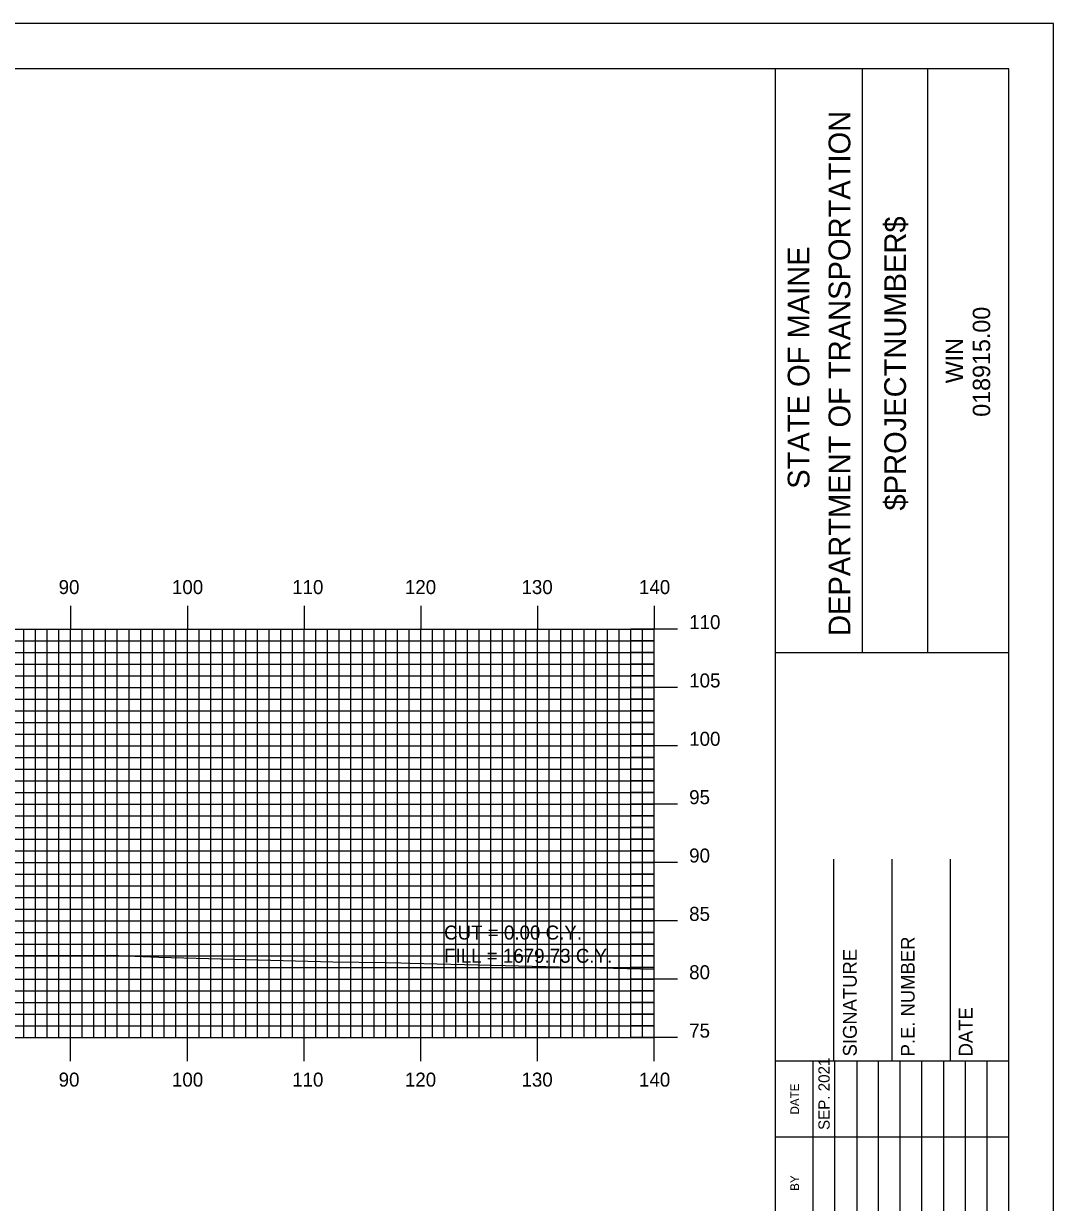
# Model space of a CAD drawing. Extents: x 852542 to 852886, y 364366 to 364586.
# Drawn here: x 852794.1 to 852882.4, y 364484.7 to 364585.7 of the extents above; entities that cross this region are included whole.
import ezdxf

# ---------------------------------------------------------------- set-up
doc = ezdxf.new("R2010")
doc.units = 0
for name, color, linetype in [('BORDER', 7, 'Continuous'), ('D_Text_Standard', 7, 'Continuous'), ('H_V ANNOTATION', 7, 'Continuous'), ('MAJOR', 7, 'Continuous'), ('MINOR', 7, 'Continuous'), ('PLOT BOUNDARY', 7, 'Continuous'), ('S_Roadway_Centerline', 7, 'Continuous')]:
    doc.layers.add(name, color=color, linetype=linetype)

msp = doc.modelspace()

# ---------------------------------------------------------------- linework, layer by layer
at = {"layer": 'BORDER'}
for p, q in [((852858.58, 364371.79), (852858.58, 364581.79)), ((852866.04, 364531.78), (852866.04, 364581.78)), ((852871.63, 364531.78), (852871.63, 364581.78)), ((852858.58, 364531.78), (852878.58, 364531.78)), ((852863.58, 364496.79), (852863.58, 364514.09)), ((852868.58, 364496.79), (852868.58, 364514.09)), ((852873.58, 364496.79), (852873.58, 364514.09)), ((852858.58, 364496.79), (852878.58, 364496.79))]:
    msp.add_line(p, q, dxfattribs=at)
msp.add_lwpolyline([(852558.58, 364371.79), (852878.58, 364371.79), (852878.58, 364581.79), (852558.58, 364581.79)], close=True, dxfattribs=at)
for points in [[(852861.81, 364490.29), (852861.81, 364496.79)], [(852863.67, 364461.8), (852863.67, 364496.79)], [(852865.54, 364496.79), (852865.54, 364461.8)], [(852867.4, 364461.8), (852867.4, 364496.79)], [(852869.26, 364461.8), (852869.26, 364496.79)], [(852871.13, 364461.8), (852871.13, 364496.79)], [(852872.99, 364461.8), (852872.99, 364496.79)], [(852874.85, 364461.8), (852874.85, 364496.79)], [(852876.72, 364461.8), (852876.72, 364496.79)], [(852861.81, 364461.8), (852861.81, 364495.38)], [(852858.58, 364490.29), (852878.58, 364490.29)]]:
    msp.add_lwpolyline(points, dxfattribs=at)
at = {"layer": 'MAJOR'}
for p, q in [((852798.18, 364535.79), (852798.18, 364533.79)), ((852808.18, 364535.79), (852808.18, 364533.79)), ((852818.18, 364535.79), (852818.18, 364533.79)), ((852828.18, 364535.79), (852828.18, 364533.79)), ((852838.18, 364535.79), (852838.18, 364533.79)), ((852848.18, 364535.79), (852848.18, 364533.79)), ((852568.18, 364533.79), (852848.18, 364533.79)), ((852568.18, 364533.79), (852848.18, 364533.79)), ((852798.18, 364498.79), (852798.18, 364533.79)), ((852808.18, 364498.79), (852808.18, 364533.79)), ((852818.18, 364498.79), (852818.18, 364533.79)), ((852828.18, 364498.79), (852828.18, 364533.79)), ((852838.18, 364498.79), (852838.18, 364533.79)), ((852850.18, 364533.79), (852846.17, 364533.79)), ((852848.18, 364498.79), (852848.18, 364533.79)), ((852848.18, 364498.79), (852848.18, 364533.79)), ((852568.18, 364528.79), (852848.18, 364528.79)), ((852850.18, 364528.79), (852846.17, 364528.79)), ((852568.18, 364523.79), (852848.18, 364523.79)), ((852850.18, 364523.79), (852846.17, 364523.79)), ((852568.18, 364518.79), (852848.18, 364518.79)), ((852850.18, 364518.79), (852846.17, 364518.79)), ((852568.18, 364513.79), (852848.18, 364513.79)), ((852850.18, 364513.79), (852846.17, 364513.79)), ((852568.18, 364508.79), (852848.18, 364508.79)), ((852850.18, 364508.79), (852846.17, 364508.79)), ((852568.18, 364503.79), (852848.18, 364503.79)), ((852850.18, 364503.79), (852846.17, 364503.79)), ((852568.18, 364498.79), (852848.18, 364498.79)), ((852568.18, 364498.79), (852848.18, 364498.79)), ((852798.18, 364496.78), (852798.18, 364498.79)), ((852808.18, 364496.78), (852808.18, 364498.79)), ((852818.18, 364496.78), (852818.18, 364498.79)), ((852828.18, 364496.78), (852828.18, 364498.79)), ((852838.18, 364496.78), (852838.18, 364498.79)), ((852850.18, 364498.79), (852846.17, 364498.79)), ((852848.18, 364496.78), (852848.18, 364498.79))]:
    msp.add_line(p, q, dxfattribs=at)
at = {"layer": 'MINOR'}
for p, q in [((852794.18, 364498.79), (852794.18, 364533.79)), ((852795.18, 364498.79), (852795.18, 364533.79)), ((852796.18, 364498.79), (852796.18, 364533.79)), ((852797.18, 364498.79), (852797.18, 364533.79)), ((852799.18, 364498.79), (852799.18, 364533.79)), ((852800.18, 364498.79), (852800.18, 364533.79)), ((852801.18, 364498.79), (852801.18, 364533.79)), ((852802.18, 364498.79), (852802.18, 364533.79)), ((852803.18, 364498.79), (852803.18, 364533.79)), ((852804.18, 364498.79), (852804.18, 364533.79)), ((852805.18, 364498.79), (852805.18, 364533.79)), ((852806.18, 364498.79), (852806.18, 364533.79)), ((852807.18, 364498.79), (852807.18, 364533.79)), ((852809.18, 364498.79), (852809.18, 364533.79)), ((852810.18, 364498.79), (852810.18, 364533.79)), ((852811.18, 364498.79), (852811.18, 364533.79)), ((852812.18, 364498.79), (852812.18, 364533.79)), ((852813.18, 364498.79), (852813.18, 364533.79)), ((852814.18, 364498.79), (852814.18, 364533.79)), ((852815.18, 364498.79), (852815.18, 364533.79)), ((852816.18, 364498.79), (852816.18, 364533.79)), ((852817.18, 364498.79), (852817.18, 364533.79)), ((852819.18, 364498.79), (852819.18, 364533.79)), ((852820.18, 364498.79), (852820.18, 364533.79)), ((852821.18, 364498.79), (852821.18, 364533.79)), ((852822.18, 364498.79), (852822.18, 364533.79)), ((852823.18, 364498.79), (852823.18, 364533.79)), ((852824.18, 364498.79), (852824.18, 364533.79)), ((852825.18, 364498.79), (852825.18, 364533.79)), ((852826.18, 364498.79), (852826.18, 364533.79)), ((852827.18, 364498.79), (852827.18, 364533.79)), ((852829.18, 364498.79), (852829.18, 364533.79)), ((852830.18, 364498.79), (852830.18, 364533.79)), ((852831.18, 364498.79), (852831.18, 364533.79)), ((852832.18, 364498.79), (852832.18, 364533.79)), ((852833.18, 364498.79), (852833.18, 364533.79)), ((852834.18, 364498.79), (852834.18, 364533.79)), ((852835.18, 364498.79), (852835.18, 364533.79)), ((852836.18, 364498.79), (852836.18, 364533.79)), ((852837.18, 364498.79), (852837.18, 364533.79)), ((852839.18, 364498.79), (852839.18, 364533.79)), ((852840.18, 364498.79), (852840.18, 364533.79)), ((852841.18, 364498.79), (852841.18, 364533.79)), ((852842.18, 364498.79), (852842.18, 364533.79)), ((852843.18, 364498.79), (852843.18, 364533.79)), ((852844.18, 364498.79), (852844.18, 364533.79)), ((852845.18, 364498.79), (852845.18, 364533.79)), ((852846.18, 364498.79), (852846.18, 364533.79)), ((852847.18, 364498.79), (852847.18, 364533.79)), ((852568.18, 364532.79), (852848.18, 364532.79)), ((852848.18, 364532.79), (852846.17, 364532.79)), ((852568.18, 364531.79), (852848.18, 364531.79)), ((852848.18, 364531.79), (852846.17, 364531.79)), ((852568.18, 364530.79), (852848.18, 364530.79)), ((852848.18, 364530.79), (852846.17, 364530.79)), ((852568.18, 364529.79), (852848.18, 364529.79)), ((852848.18, 364529.79), (852846.17, 364529.79)), ((852568.18, 364527.79), (852848.18, 364527.79)), ((852848.18, 364527.79), (852846.17, 364527.79)), ((852568.18, 364526.79), (852848.18, 364526.79)), ((852848.18, 364526.79), (852846.17, 364526.79)), ((852568.18, 364525.79), (852848.18, 364525.79)), ((852848.18, 364525.79), (852846.17, 364525.79)), ((852568.18, 364524.79), (852848.18, 364524.79)), ((852848.18, 364524.79), (852846.17, 364524.79)), ((852568.18, 364522.79), (852848.18, 364522.79)), ((852848.18, 364522.79), (852846.17, 364522.79)), ((852568.18, 364521.79), (852848.18, 364521.79)), ((852848.18, 364521.79), (852846.17, 364521.79)), ((852568.18, 364520.79), (852848.18, 364520.79)), ((852848.18, 364520.79), (852846.17, 364520.79)), ((852568.18, 364519.79), (852848.18, 364519.79)), ((852848.18, 364519.79), (852846.17, 364519.79)), ((852568.18, 364517.79), (852848.18, 364517.79)), ((852848.18, 364517.79), (852846.17, 364517.79)), ((852568.18, 364516.79), (852848.18, 364516.79)), ((852848.18, 364516.79), (852846.17, 364516.79)), ((852568.18, 364515.79), (852848.18, 364515.79)), ((852848.18, 364515.79), (852846.17, 364515.79)), ((852568.18, 364514.79), (852848.18, 364514.79)), ((852848.18, 364514.79), (852846.17, 364514.79)), ((852568.18, 364512.79), (852848.18, 364512.79)), ((852848.18, 364512.79), (852846.17, 364512.79)), ((852568.18, 364511.79), (852848.18, 364511.79)), ((852848.18, 364511.79), (852846.17, 364511.79)), ((852568.18, 364510.79), (852848.18, 364510.79)), ((852848.18, 364510.79), (852846.17, 364510.79)), ((852568.18, 364509.79), (852848.18, 364509.79)), ((852848.18, 364509.79), (852846.17, 364509.79)), ((852568.18, 364507.79), (852848.18, 364507.79)), ((852848.18, 364507.79), (852846.17, 364507.79)), ((852568.18, 364506.79), (852848.18, 364506.79)), ((852848.18, 364506.79), (852846.17, 364506.79)), ((852568.18, 364505.79), (852848.18, 364505.79)), ((852848.18, 364505.79), (852846.17, 364505.79)), ((852568.18, 364504.79), (852848.18, 364504.79)), ((852848.18, 364504.79), (852846.17, 364504.79)), ((852568.18, 364502.79), (852848.18, 364502.79)), ((852848.18, 364502.79), (852846.17, 364502.79)), ((852568.18, 364501.79), (852848.18, 364501.79)), ((852848.18, 364501.79), (852846.17, 364501.79)), ((852568.18, 364500.79), (852848.18, 364500.79)), ((852848.18, 364500.79), (852846.17, 364500.79)), ((852568.18, 364499.79), (852848.18, 364499.79)), ((852848.18, 364499.79), (852846.17, 364499.79))]:
    msp.add_line(p, q, dxfattribs=at)
at = {"layer": 'PLOT BOUNDARY'}
msp.add_lwpolyline([(852542.39, 364365.67), (852882.39, 364365.67), (852882.39, 364585.67), (852542.39, 364585.67)], close=True, dxfattribs=at)
at = {"layer": 'S_Roadway_Centerline'}
msp.add_lwpolyline([(852688.24, 364505.51), (852704.86, 364505.68), (852713.61, 364505.59), (852717.09, 364505.47), (852723.54, 364505.56), (852751.09, 364505.36), (852753.15, 364505.3), (852757.09, 364505.41), (852769.63, 364505.6), (852782.33, 364505.81), (852787.57, 364505.85), (852792.86, 364505.83), (852801.61, 364505.86), (852805.73, 364505.68), (852820.64, 364505.29), (852825.12, 364505.22), (852826.46, 364505.21), (852827.26, 364505.17), (852848.18, 364504.66)], dxfattribs=at)

# ---------------------------------------------------------------- texts
at = {"layer": 'BORDER'}
for s, height, p in [('DEPARTMENT OF TRANSPORTATION', 1.8635, (852864.99, 364533.2)), ('$PROJECTNUMBER$', 1.8635, (852869.76, 364543.95)), ('STATE OF MAINE', 1.8635, (852861.49, 364545.81)), ('018915.00', 1.491, (852876.97, 364551.98)), ('WIN', 1.491, (852874.65, 364554.85)), ('P.E. NUMBER', 1.1811, (852870.5, 364497.18)), ('SIGNATURE', 1.181, (852865.54, 364497.18)), ('DATE', 1.181, (852875.46, 364497.18)), ('SEP. 2021', 0.969, (852863.22, 364490.88)), ('DATE', 0.743, (852860.59, 364492.2)), ('BY', 0.743, (852860.59, 364485.66))]:
    msp.add_text(s, height=height, rotation=90, dxfattribs=at).set_placement(p)
at = {"layer": 'D_Text_Standard'}
for s, p in [('CUT = 0.00 C.Y.', (852830.18, 364507.19)), ('FILL = 1679.73 C.Y.', (852830.18, 364505.2))]:
    msp.add_text(s, height=1.2, dxfattribs=at).set_placement(p)
at = {"layer": 'H_V ANNOTATION'}
for s, p in [('90', (852797.15, 364536.79)), ('100', (852806.86, 364536.79)), ('110', (852817.16, 364536.79)), ('120', (852826.82, 364536.79)), ('130', (852836.81, 364536.79)), ('140', (852846.88, 364536.79)), ('110', (852851.18, 364533.79)), ('105', (852851.18, 364528.79)), ('100', (852851.18, 364523.79)), ('95', (852851.18, 364518.79)), ('90', (852851.18, 364513.79)), ('85', (852851.18, 364508.79)), ('80', (852851.18, 364503.79)), ('75', (852851.18, 364498.79)), ('90', (852797.15, 364494.59)), ('100', (852806.86, 364494.59)), ('110', (852817.16, 364494.59)), ('120', (852826.82, 364494.59)), ('130', (852836.81, 364494.59)), ('140', (852846.88, 364494.59))]:
    msp.add_text(s, height=1.2, dxfattribs=at).set_placement(p)

doc.saveas('drawing.dxf')
